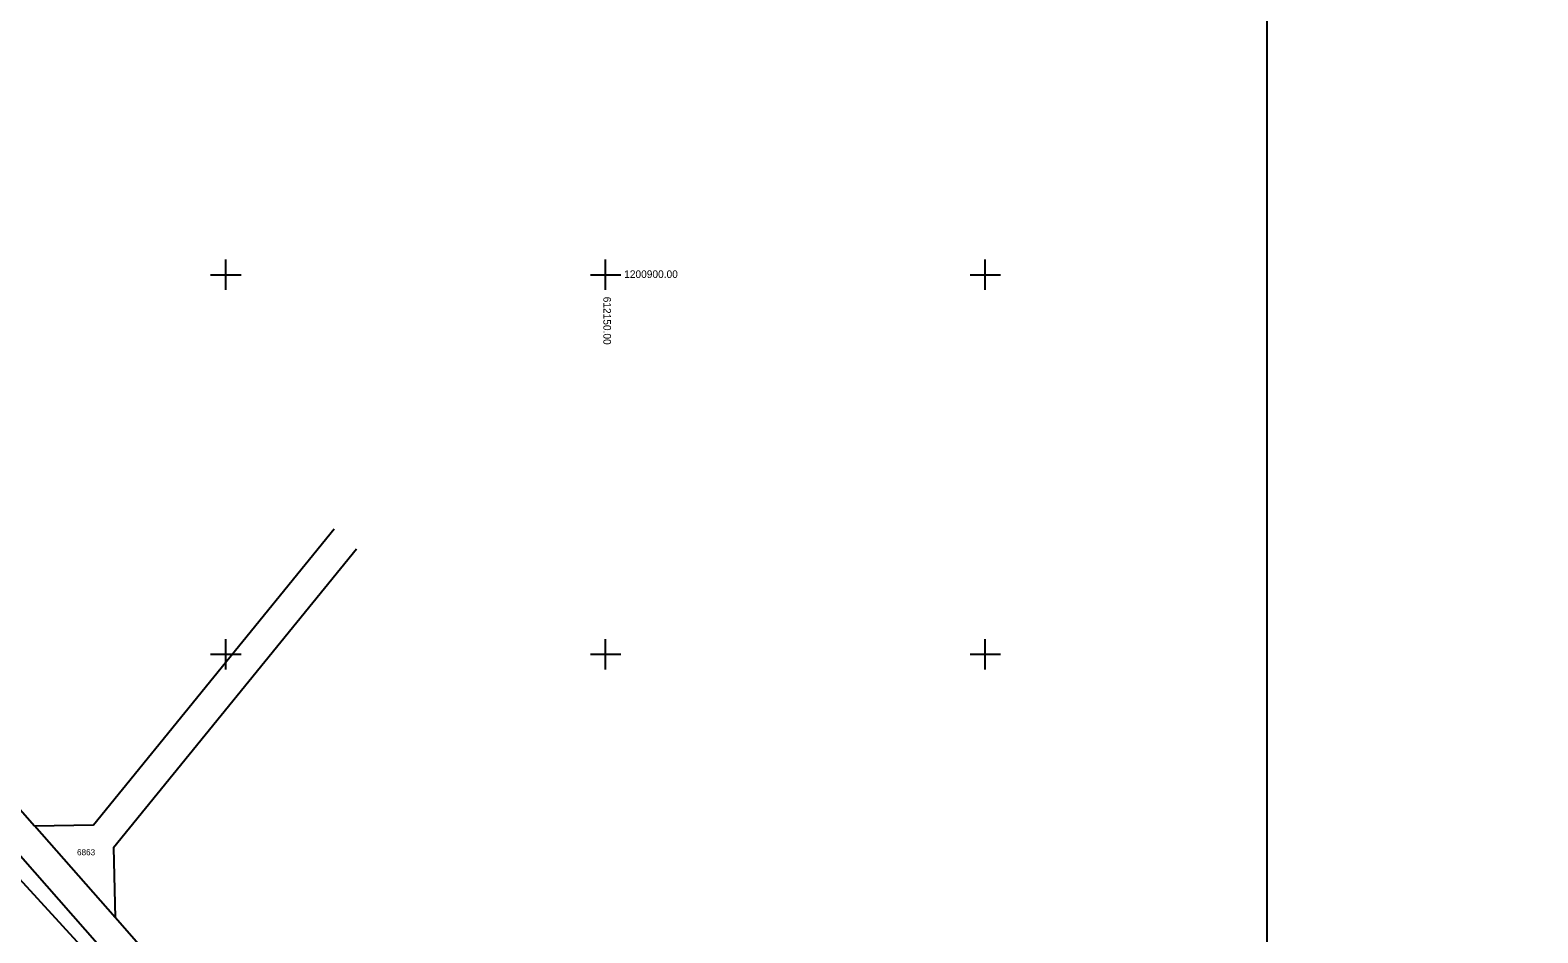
# Model space of a CAD drawing. Extents: x -612546 to -611926, y -1201932 to -1200444.
# Drawn here: x -612225.8 to -612027.2, y -1200986.7 to -1200867.8 of the extents above; entities that cross this region are included whole.
import ezdxf

# ---------------------------------------------------------------- set-up
doc = ezdxf.new("R2010")
doc.units = 0
for name, color, linetype in [('14 hrana pata svahu', 7, 'Continuous'), ('61 legenda křížky', 7, 'Continuous'), ('Hranice parcel', 7, 'Continuous'), ('Parcelní čísla', 7, 'Continuous'), ('Vrstva 63', 7, 'Continuous')]:
    doc.layers.add(name, color=color, linetype=linetype)

msp = doc.modelspace()

# ---------------------------------------------------------------- linework, layer by layer
at = {"layer": '14 hrana pata svahu'}
msp.add_lwpolyline([(-612115.84, -1201111.42), (-612142.3, -1201080.92), (-612162.58, -1201054.92), (-612187.22, -1201025.94), (-612211.45, -1200996.73), (-612237.71, -1200968.13), (-612275.47, -1200925.26), (-612297.25, -1200898.18), (-612305.42, -1200888.34), (-612310.59, -1200874.11), (-612323.74, -1200837.38), (-612336.44, -1200801.43), (-612350.12, -1200764.09), (-612361.57, -1200731.35), (-612377.95, -1200692.77), (-612388.38, -1200663.69), (-612401.66, -1200625.89), (-612414.44, -1200590.59), (-612427.78, -1200553.92), (-612436.33, -1200532.1), (-612442.76, -1200519.02), (-612455.83, -1200502.43), (-612463.71, -1200487.36), (-612471.87, -1200478.15)], dxfattribs=at)
at = {"layer": '61 legenda křížky'}
for p, q in [((-612200, -1200902), (-612200, -1200898)), ((-612150, -1200902), (-612150, -1200898)), ((-612100, -1200902), (-612100, -1200898)), ((-612202, -1200900), (-612198, -1200900)), ((-612152, -1200900), (-612148, -1200900)), ((-612102, -1200900), (-612098, -1200900)), ((-612200, -1200952), (-612200, -1200948)), ((-612150, -1200952), (-612150, -1200948)), ((-612100, -1200952), (-612100, -1200948)), ((-612202, -1200950), (-612198, -1200950)), ((-612152, -1200950), (-612148, -1200950)), ((-612102, -1200950), (-612098, -1200950))]:
    msp.add_line(p, q, dxfattribs=at)
at = {"layer": 'Hranice parcel'}
msp.add_line((-612214.59, -1200984.67), (-612225.19, -1200972.6), dxfattribs=at)
for points in [[(-612424.14, -1200544.19), (-612385.56, -1200652.97), (-612376.97, -1200665.68), (-612365.31, -1200671.92), (-612359.59, -1200681.01), (-612363.6, -1200702.67), (-612362.5, -1200716.42), (-612304.9, -1200876.31), (-612299.88, -1200886.48), (-612289.63, -1200899.21), (-612225.19, -1200972.6)], [(-612367.63, -1200702.46), (-612366.44, -1200717.27), (-612308.59, -1200877.88), (-612303.27, -1200888.65), (-612292.69, -1200901.79), (-612203.37, -1201003.51), (-612163.72, -1201050.75), (-612139.89, -1201080.24), (-612084.23, -1201147.54), (-612068.31, -1201163.86)], [(-612225.19, -1200972.6), (-612217.44, -1200972.46), (-612185.75, -1200933.48)], [(-612182.78, -1200936.16), (-612214.77, -1200975.5), (-612214.59, -1200984.67)], [(-612027.25, -1201146.78), (-612057.59, -1201153.91), (-612067.61, -1201153.97), (-612081.25, -1201144.86), (-612136.79, -1201077.71), (-612160.63, -1201048.21), (-612200.33, -1201000.9), (-612214.59, -1200984.67)]]:
    msp.add_lwpolyline(points, dxfattribs=at)
at = {"layer": 'Vrstva 63'}
msp.add_line((-612062.93, -1200831.26), (-612062.93, -1201251.26), dxfattribs=at)

# ---------------------------------------------------------------- texts
at = {"layer": '61 legenda křížky'}
msp.add_text('1200900.00', height=1, dxfattribs=at).set_placement((-612147.55, -1200900.43))
msp.add_text('612150.00', height=1, rotation=270, dxfattribs=at).set_placement((-612150.29, -1200902.9))
at = {"layer": 'Parcelní čísla'}
msp.add_text('6863', height=0.8, dxfattribs=at).set_placement((-612219.59, -1200976.48))

doc.saveas('drawing.dxf')
